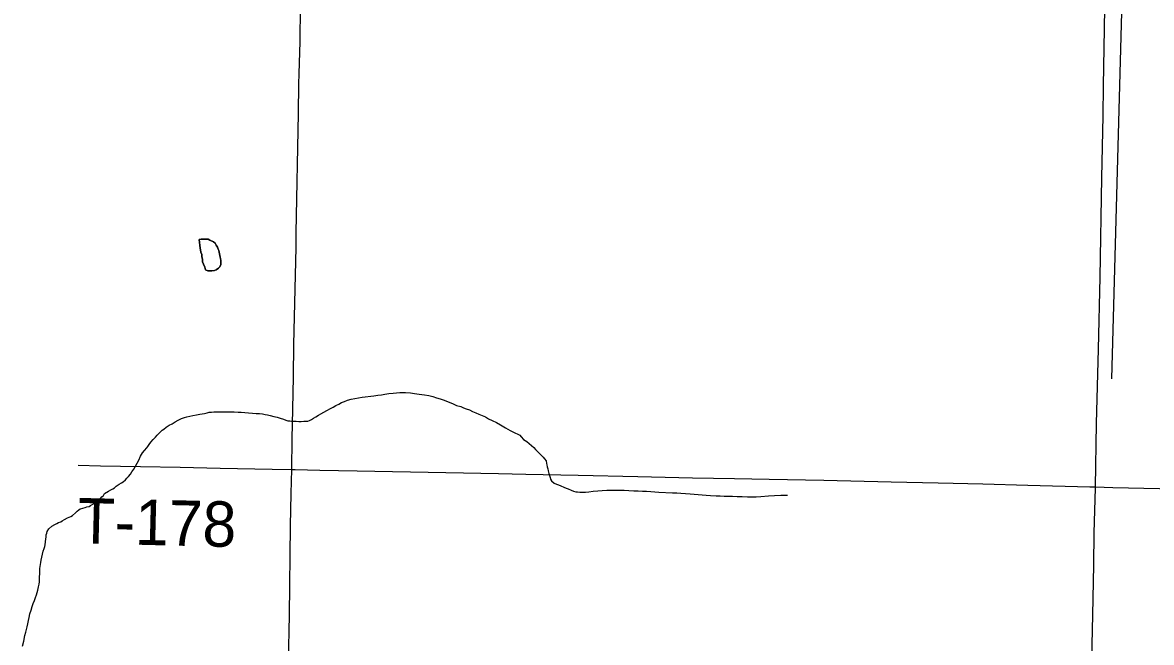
# Model space of a CAD drawing. Extents: x 2.1 to 73.9, y 4 to 26.
# Drawn here: x 47.406 to 48.112, y 19.167 to 19.554 of the extents above; entities that cross this region are included whole.
import ezdxf

# ---------------------------------------------------------------- set-up
doc = ezdxf.new("R2010")
doc.units = 0
for name, color, linetype in [('GM_X_Minor_Lake', 7, 'Continuous'), ('GM_X_Minor_River', 7, 'Continuous'), ('GM_X_Township_Road', 7, 'Continuous'), ('GM_X_Township_Road_Text', 7, 'Continuous')]:
    doc.layers.add(name, color=color, linetype=linetype)

msp = doc.modelspace()

# ---------------------------------------------------------------- linework, layer by layer
at = {"layer": 'GM_X_Minor_Lake'}
for points in [[(47.52978, 19.40474), (47.52978, 19.40569), (47.5296, 19.40683), (47.52941, 19.40778), (47.52922, 19.40873), (47.52903, 19.40987), (47.52884, 19.41083), (47.52846, 19.41178), (47.52809, 19.41273), (47.52771, 19.41387), (47.52695, 19.4152), (47.52619, 19.41653), (47.52524, 19.4173), (47.52296, 19.41844), (47.52182, 19.41902), (47.5203, 19.41902), (47.51916, 19.41903), (47.51745, 19.41903), (47.51631, 19.41884)], [(47.51631, 19.41884), (47.51745, 19.41903), (47.51916, 19.41903), (47.5203, 19.41902), (47.52182, 19.41902), (47.52296, 19.41844), (47.52524, 19.4173), (47.52619, 19.41653), (47.52695, 19.4152), (47.52771, 19.41387), (47.52809, 19.41273), (47.52846, 19.41178), (47.52884, 19.41083), (47.52903, 19.40987), (47.52922, 19.40873), (47.52941, 19.40778), (47.5296, 19.40683), (47.52978, 19.40569), (47.52978, 19.40474), (47.52978, 19.40322), (47.5292, 19.4017), (47.52825, 19.40075), (47.52692, 19.39981), (47.52578, 19.39943), (47.52426, 19.39925), (47.52255, 19.39925), (47.52159, 19.39925), (47.52026, 19.39983), (47.5197, 19.40135), (47.51894, 19.40325), (47.51837, 19.40477), (47.51838, 19.4063), (47.518, 19.4082), (47.51781, 19.40934), (47.51724, 19.41086), (47.51706, 19.41238), (47.51687, 19.41333), (47.51631, 19.41884)], [(47.51631, 19.41884), (47.51687, 19.41333), (47.51706, 19.41238), (47.51724, 19.41086), (47.51781, 19.40934), (47.518, 19.4082), (47.51838, 19.4063), (47.51837, 19.40477), (47.51894, 19.40325), (47.5197, 19.40135), (47.52026, 19.39983), (47.52159, 19.39925), (47.52255, 19.39925), (47.52426, 19.39925), (47.52578, 19.39943), (47.52692, 19.39981), (47.52825, 19.40075), (47.5292, 19.4017), (47.52978, 19.40322), (47.52978, 19.40474)]]:
    msp.add_lwpolyline(points, dxfattribs=at)
at = {"layer": 'GM_X_Minor_River'}
for points in [[(48.0949, 19.61482), (48.0871, 19.33166)], [(47.46771, 19.26656), (47.46866, 19.26713), (47.47019, 19.26846), (47.47095, 19.26941), (47.47209, 19.27054), (47.47323, 19.27187), (47.47419, 19.27339), (47.47533, 19.27509), (47.47629, 19.27699), (47.47743, 19.27889), (47.47839, 19.28079), (47.47953, 19.28325), (47.48087, 19.28534), (47.48201, 19.28667), (47.48353, 19.28837), (47.48411, 19.28932), (47.48487, 19.29046), (47.48601, 19.29198), (47.48754, 19.29368), (47.48887, 19.29501), (47.49001, 19.29634), (47.49097, 19.29747), (47.49211, 19.29842), (47.49306, 19.29937), (47.49421, 19.30012), (47.49554, 19.30145), (47.49744, 19.30259), (47.49935, 19.30353), (47.50125, 19.30467), (47.50315, 19.3058), (47.50525, 19.30674), (47.50696, 19.3075), (47.50848, 19.30787), (47.51229, 19.30862), (47.51457, 19.309), (47.51666, 19.30956), (47.51951, 19.30993), (47.52123, 19.31031), (47.52256, 19.31069), (47.52389, 19.31068), (47.52541, 19.31087), (47.53016, 19.31085), (47.53187, 19.31085), (47.53396, 19.31084), (47.53606, 19.31103), (47.53815, 19.31102), (47.54062, 19.31082), (47.54252, 19.31082), (47.5448, 19.31043), (47.54708, 19.31023), (47.54955, 19.31003), (47.55183, 19.30984), (47.55393, 19.30983), (47.55583, 19.30964), (47.55754, 19.30925), (47.55906, 19.30906), (47.56058, 19.30867), (47.56286, 19.3081), (47.56495, 19.30752), (47.56685, 19.30694), (47.56894, 19.30637), (47.57046, 19.30579), (47.57179, 19.30541), (47.57293, 19.30522), (47.57407, 19.30502), (47.57521, 19.30502), (47.57692, 19.30501), (47.57863, 19.30482), (47.58016, 19.30481), (47.58168, 19.305), (47.58301, 19.305), (47.58415, 19.30518), (47.58529, 19.30556), (47.58643, 19.30613), (47.58776, 19.30707), (47.58929, 19.30783), (47.59081, 19.30877), (47.59233, 19.30972), (47.59424, 19.31066), (47.59614, 19.3118), (47.59842, 19.31293), (47.60014, 19.31388), (47.60185, 19.31482), (47.60356, 19.31577), (47.60528, 19.31671), (47.60718, 19.31747), (47.60908, 19.31822), (47.61137, 19.31879), (47.61365, 19.31935), (47.61593, 19.31972), (47.61821, 19.3201), (47.62563, 19.32103), (47.6281, 19.3214), (47.63038, 19.32158), (47.63248, 19.32196), (47.63495, 19.32233), (47.63761, 19.3227), (47.6397, 19.32289), (47.64179, 19.32307), (47.6437, 19.32306), (47.64541, 19.32306)], [(47.64541, 19.32306), (47.64845, 19.32286), (47.65092, 19.32247), (47.65396, 19.32208), (47.65719, 19.3215), (47.66004, 19.32112), (47.66251, 19.32054), (47.66479, 19.31977), (47.66707, 19.319), (47.66954, 19.31824), (47.67201, 19.31728), (47.67467, 19.31613), (47.67733, 19.31498), (47.67999, 19.31421), (47.6817, 19.31345), (47.68341, 19.31287), (47.68531, 19.31211), (47.68721, 19.31115), (47.6893, 19.31039), (47.6912, 19.30943), (47.69329, 19.30866), (47.69538, 19.30771), (47.69728, 19.30656), (47.69956, 19.30561), (47.70222, 19.30427), (47.70488, 19.30274), (47.70792, 19.30102), (47.71095, 19.2993), (47.7138, 19.29777), (47.7157, 19.29701), (47.71684, 19.29624), (47.71779, 19.29529), (47.71912, 19.29358), (47.72121, 19.29243), (47.72273, 19.29109), (47.72424, 19.28995), (47.72557, 19.28862), (47.72671, 19.28747), (47.73032, 19.28385), (47.73146, 19.28252), (47.7324, 19.28156), (47.73335, 19.28023), (47.73354, 19.27871), (47.73373, 19.27776), (47.7341, 19.27662), (47.73448, 19.27529), (47.73467, 19.27395), (47.73505, 19.27243), (47.73542, 19.2711), (47.7358, 19.26996), (47.73618, 19.26882), (47.73675, 19.26787), (47.73846, 19.26634), (47.73979, 19.26577), (47.74112, 19.26519), (47.74264, 19.26462), (47.74435, 19.26385), (47.74587, 19.26328), (47.7472, 19.26271), (47.74909, 19.26194), (47.75042, 19.26137), (47.75194, 19.26098), (47.75309, 19.26079), (47.75442, 19.26059), (47.75594, 19.26059), (47.75803, 19.26077), (47.76012, 19.26096), (47.76278, 19.26133), (47.76564, 19.26151), (47.76849, 19.26169), (47.77134, 19.26187), (47.77571, 19.26186), (47.77895, 19.26185), (47.78218, 19.26184), (47.78522, 19.26164), (47.78826, 19.26145), (47.79092, 19.26144), (47.79358, 19.26124), (47.79625, 19.26123), (47.79891, 19.26103), (47.80138, 19.26084), (47.80385, 19.26064), (47.81241, 19.26023), (47.81507, 19.26023), (47.81773, 19.26003), (47.82058, 19.25983), (47.82343, 19.25963), (47.82609, 19.25944), (47.82857, 19.25924), (47.83104, 19.25904), (47.83351, 19.25884), (47.83617, 19.25865), (47.83978, 19.25845), (47.84225, 19.25844), (47.84472, 19.25824), (47.84739, 19.25823), (47.85005, 19.25823), (47.8529, 19.25803), (47.85613, 19.25802), (47.85936, 19.25782), (47.86202, 19.25781)], [(47.40572, 19.1643), (47.40648, 19.16753), (47.40706, 19.17095), (47.40782, 19.17304), (47.40821, 19.17475), (47.40859, 19.17646), (47.40898, 19.17836), (47.40936, 19.18045), (47.40974, 19.18235), (47.41032, 19.18463), (47.41108, 19.18691), (47.41166, 19.18919), (47.41242, 19.19108), (47.41319, 19.19298), (47.41376, 19.19488), (47.41433, 19.1964), (47.41491, 19.19792), (47.41529, 19.19944), (47.41568, 19.20153), (47.41606, 19.20305), (47.41625, 19.20457), (47.41626, 19.20609), (47.41626, 19.20761), (47.41645, 19.20951), (47.41646, 19.21293), (47.41703, 19.2154), (47.41723, 19.21673), (47.41742, 19.21806), (47.41819, 19.22186), (47.41857, 19.22375), (47.41915, 19.22546), (47.41972, 19.2266), (47.41991, 19.22774), (47.4201, 19.22964), (47.4203, 19.23154), (47.42049, 19.23249), (47.42049, 19.23401), (47.42088, 19.23496), (47.42107, 19.2361), (47.42221, 19.23781), (47.42412, 19.23951), (47.42583, 19.24046), (47.42716, 19.24103), (47.4283, 19.24178), (47.42964, 19.24216), (47.43059, 19.24273), (47.43192, 19.24367), (47.43382, 19.24462), (47.43592, 19.24556), (47.43687, 19.24613), (47.43877, 19.24783), (47.43992, 19.24878), (47.44087, 19.24973), (47.44182, 19.2503), (47.44353, 19.25067), (47.44486, 19.25105), (47.44601, 19.25142), (47.44734, 19.2518), (47.44829, 19.25237), (47.44962, 19.25312), (47.45114, 19.25407), (47.45267, 19.25539), (47.45419, 19.25653), (47.45533, 19.25767), (47.45629, 19.25861), (47.45705, 19.25975), (47.45952, 19.26127), (47.46086, 19.26221), (47.46219, 19.26278), (47.46314, 19.26335), (47.46428, 19.26448), (47.46619, 19.26562), (47.46771, 19.26656)], [(47.86202, 19.25781), (47.86488, 19.2578), (47.86773, 19.25798), (47.87248, 19.25835), (47.87629, 19.25853), (47.88028, 19.25871), (47.88408, 19.2587), (47.88449, 19.2587)]]:
    msp.add_lwpolyline(points, dxfattribs=at)
at = {"layer": 'GM_X_Township_Road'}
for points in [[(47.57415, 19.27487), (47.57452, 19.29399), (47.57478, 19.31264), (47.57525, 19.33285), (47.57552, 19.35305), (47.57694, 19.41366), (47.5769, 19.42298), (47.57844, 19.49759), (47.57864, 19.51624), (47.57885, 19.52245), (47.57936, 19.54266), (47.57962, 19.56441), (47.57987, 19.59239), (47.58023, 19.61726), (47.58041, 19.63124), (47.58083, 19.65455), (47.58151, 19.69185), (47.58216, 19.72759), (47.58241, 19.74157), (47.58263, 19.75554), (47.58287, 19.76951), (47.58322, 19.77769)], [(48.07715, 19.264), (48.07779, 19.30354), (48.07902, 19.35015), (48.08, 19.39522), (48.08117, 19.45738), (48.08192, 19.49623), (48.0822, 19.51488), (48.0829, 19.55063), (48.08329, 19.57705), (48.08387, 19.60191), (48.08437, 19.62677), (48.08458, 19.64226), (48.08524, 19.67806), (48.0857, 19.70137), (48.08596, 19.7138), (48.0864, 19.73245), (48.08717, 19.76663), (48.08718, 19.76753)], [(47.44056, 19.27752), (47.45457, 19.27709), (47.47949, 19.27671), (47.5044, 19.27627), (47.52931, 19.27567), (47.56201, 19.27507), (47.57415, 19.27487)], [(47.56955, 19.02239), (47.57001, 19.04377), (47.57045, 19.06708), (47.57047, 19.07796), (47.57089, 19.0935), (47.57151, 19.11681), (47.57211, 19.15411), (47.57267, 19.18364), (47.5734, 19.2396), (47.57385, 19.2598), (47.57415, 19.27487)], [(47.57415, 19.27487), (47.57622, 19.27482), (47.59176, 19.27447), (47.61508, 19.27413), (47.67065, 19.27297), (47.70366, 19.27229), (47.72075, 19.27189), (47.75338, 19.27122), (47.79068, 19.27054), (47.82487, 19.26975), (47.8513, 19.26927), (47.87305, 19.26876), (47.90725, 19.26824), (47.9492, 19.26721), (47.97874, 19.26659), (48.00671, 19.26592), (48.03492, 19.26516), (48.07353, 19.26412), (48.07715, 19.264)], [(48.0718, 19.01269), (48.07198, 19.02693), (48.07341, 19.08753), (48.07388, 19.11551), (48.07474, 19.14658), (48.07544, 19.18388), (48.0762, 19.21496), (48.0764, 19.23516), (48.07714, 19.26313), (48.07715, 19.264)], [(48.07715, 19.264), (48.088, 19.2637), (48.11719, 19.26298), (48.14211, 19.26256), (48.23205, 19.26103), (48.26485, 19.26048), (48.29422, 19.25999), (48.33463, 19.25921), (48.39991, 19.2581), (48.47141, 19.25698), (48.51803, 19.25601), (48.53957, 19.25557), (48.55845, 19.2552), (48.56357, 19.25505), (48.5671, 19.25494), (48.5718, 19.2548), (48.57629, 19.25466), (48.58002, 19.25457)]]:
    msp.add_lwpolyline(points, dxfattribs=at)

# ---------------------------------------------------------------- texts
at = {"layer": 'GM_X_Township_Road_Text'}
msp.add_text('T-178', height=0.028409, rotation=358.59656, dxfattribs=at).set_placement((47.43992, 19.22872))

doc.saveas('drawing.dxf')
